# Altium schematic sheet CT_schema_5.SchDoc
size 205 x 258 mm
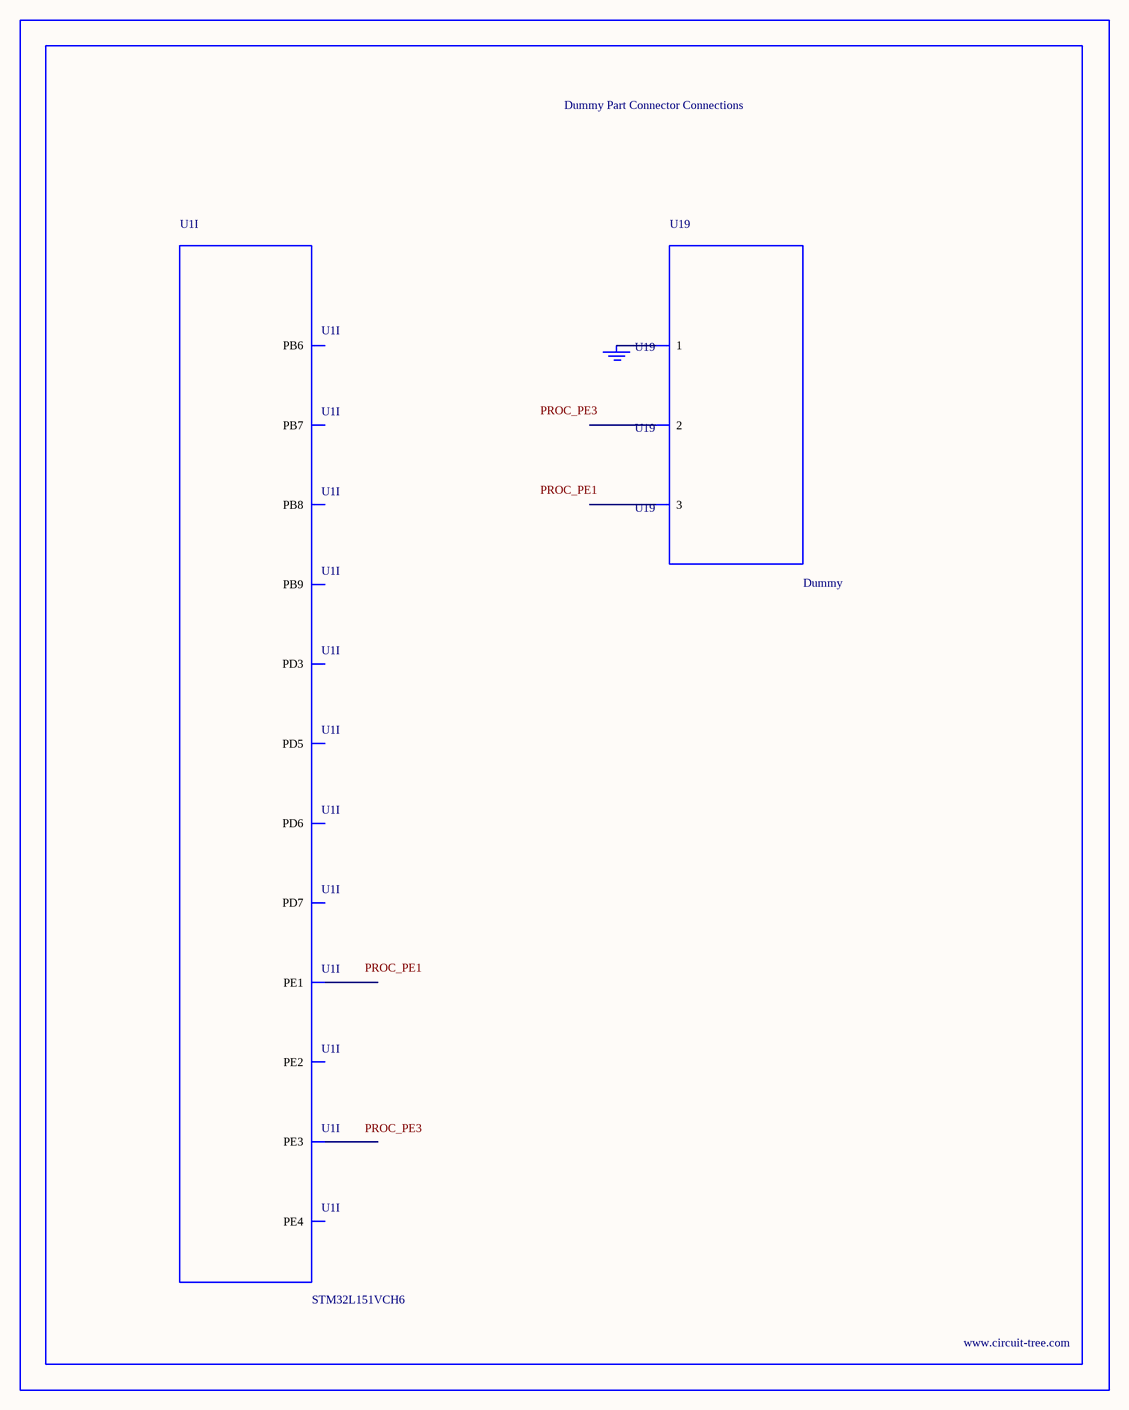
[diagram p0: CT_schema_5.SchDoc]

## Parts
BORDER4  (no value)
GND_INSTANCE_4_0  (no value)
U1  STM32L151VCH6  [UFBGA100]  (part I of 9)
U19  Dummy  [DUMMY_PACKAGE_172]

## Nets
NetGND_INSTANCE_4_0_0: GND_INSTANCE_4_0.0(GND) U19.1

Not connected (* = marked no-connect by the designer): U1 A1(PE3) A2(PE1) A3(PB8) A5(PD7) A6(PD5) B1(PE4) B2(PE2) B3(PB9) B4(PB7) B5(PB6) B6(PD6) B8(PD3); U19 2 3

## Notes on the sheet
- Labels drawn without touching a wire or pin: PROC_PE1, PROC_PE3

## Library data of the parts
BORDER4 = BORDER_PAGE4
GND_INSTANCE_4_0 = GND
